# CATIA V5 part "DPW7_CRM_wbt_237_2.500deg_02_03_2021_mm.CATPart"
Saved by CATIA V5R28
Part number: DPW7_CRM_wbt_237_2.500deg_02_03_2021
Bounding box of the stored display mesh (mm): x 2349.5 to 66711.891, y 0 to 29488.068, z 2310.119 to 8715.756
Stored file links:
  Z:\Scratch\04_CAD_Allgemein\Flight2Jig\Output\DPW-7\CATPart\DPW7_CRM_wbt_237_2.500deg_02_03_2021.CATPart
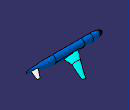
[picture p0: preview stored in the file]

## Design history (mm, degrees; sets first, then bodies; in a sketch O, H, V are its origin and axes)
Set1
  DatumSurface1 "Clean_Wing"
  DatumSurface2 "Fuselage"
  DatumSurface3 "HTP"
  DatumSurface4 "Symmetry"
  DatumSurface5 "Farfield"
Body1 (main body)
